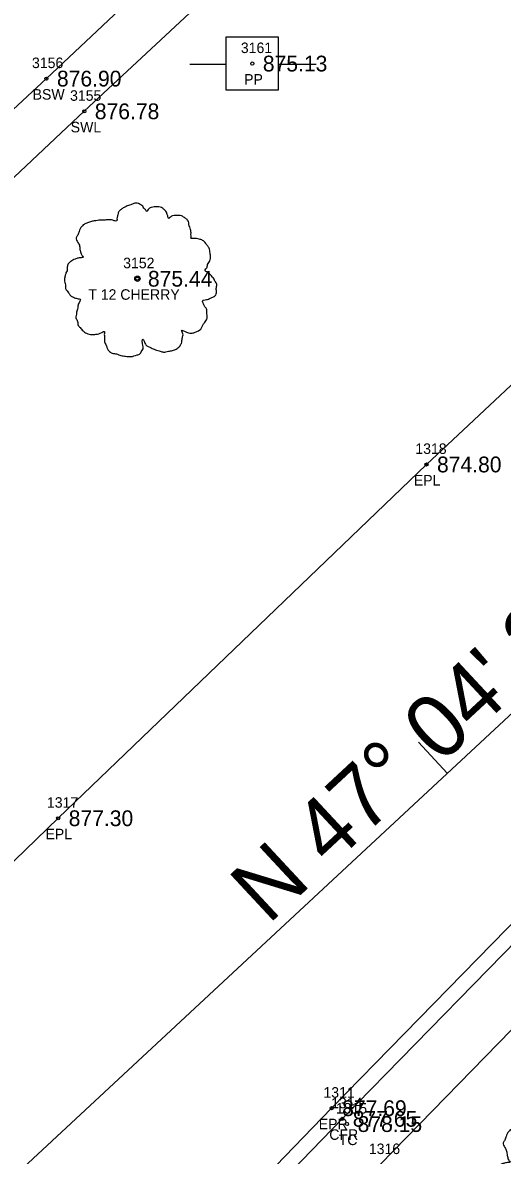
# Model space of a CAD drawing. Extents: x 1622501 to 1626664, y 1117816 to 1121579.
# Drawn here: x 1623728.6 to 1623774.2, y 1119016.9 to 1119124.7 of the extents above; entities that cross this region are included whole.
import ezdxf

# ---------------------------------------------------------------- set-up
doc = ezdxf.new("R2010")
doc.units = 0
for name, color, linetype in [('RD_EX_Conc', 7, 'Continuous'), ('RD_EX_Conc_txCode', 7, 'Continuous'), ('RD_EX_Road', 7, 'Continuous'), ('RD_EX_Road_txCode', 7, 'Continuous'), ('RD_EX_TX_Conc_ELEV', 7, 'Continuous'), ('RD_EX_TX_Road_ELEV', 7, 'Continuous'), ('RD_EX_TX_VEG_ELEV', 7, 'Continuous'), ('RD_EX_UT', 7, 'Continuous'), ('RD_EX_UT_txCode', 7, 'Continuous'), ('RD_EX_VEG', 7, 'Continuous'), ('RD_EX_VEG_txCode', 7, 'Continuous'), ('RD_HC_Cl', 7, 'Continuous'), ('RD_HC_Data', 7, 'Continuous'), ('RD_HC_Data_Tic', 7, 'Continuous'), ('RD_HC_Survey_ELEV', 7, 'Continuous'), ('RD_SMD_Locator', 7, 'Continuous')]:
    doc.layers.add(name, color=color, linetype=linetype)

msp = doc.modelspace()

# ---------------------------------------------------------------- linework, layer by layer
at = {"layer": 'RD_EX_Conc'}
for points in [[(1623595.96, 1118993.1), (1623622.15, 1119017.61), (1623656.16, 1119049.38), (1623694.84, 1119085.83), (1623730.88, 1119119.33), (1623767.2, 1119153.55), (1623807.43, 1119191.23), (1623857.13, 1119237.78)], [(1623598.76, 1118988.76), (1623625.5, 1119014.05), (1623659.65, 1119046.04), (1623697.95, 1119081.83), (1623734.48, 1119116.22), (1623770.4, 1119149.72), (1623810.51, 1119187.32), (1623859.03, 1119232.94)], [(1623723.66, 1118851.28), (1623685.69, 1118891.78), (1623680.28, 1118899.28), (1623678.54, 1118902.67), (1623678.54, 1118902.67), (1623675.57, 1118911.95), (1623675.05, 1118920.35), (1623676.57, 1118930.33), (1623679.23, 1118937.18), (1623684.43, 1118944.64), (1623689.98, 1118950.42), (1623724.5, 1118984.8), (1623759.01, 1119020.42), (1623793.7, 1119055.91), (1623829.35, 1119090.86), (1623865.61, 1119125.13), (1623901.92, 1119159.18), (1623933.22, 1119188.5)], [(1623676.3, 1118912.01), (1623681.21, 1118913.01), (1623680.58, 1118920.41), (1623681.86, 1118928.77), (1623684.24, 1118934.73), (1623688.55, 1118940.79), (1623694.15, 1118946.67), (1623728.27, 1118980.63), (1623762.62, 1119016.07), (1623797.56, 1119051.92), (1623833.1, 1119086.63), (1623869.15, 1119120.8), (1623905.55, 1119155), (1623936.97, 1119184.35), (1623933.79, 1119188.03)]]:
    msp.add_lwpolyline(points, dxfattribs=at)
at = {"layer": 'RD_EX_Road'}
for points in [[(1623722.97, 1118850.61), (1623684.95, 1118891.23), (1623679.41, 1118898.68), (1623674.26, 1118911.53), (1623673.5, 1118920.18), (1623675.21, 1118930.83), (1623677.99, 1118937.82), (1623683.61, 1118945.52), (1623688.81, 1118951.26), (1623723.47, 1118985.72), (1623758, 1119021.43), (1623792.69, 1119056.92), (1623828.41, 1119091.92), (1623864.6, 1119126.19), (1623900.88, 1119160.22), (1623932.37, 1119189.42), (1623932.63, 1119189.22), (1623935.82, 1119192.17), (1623973.77, 1119227.77), (1623990.87, 1119243.54), (1624009.99, 1119262.02), (1624046.29, 1119296.15)], [(1623613.19, 1119042.02), (1623611.01, 1119043.81), (1623609, 1119042.95), (1623599.73, 1119032.63), (1623594.94, 1119023.41), (1623593.06, 1119016.81), (1623592.29, 1119005.79), (1623594.79, 1118992.8), (1623599.51, 1118985.89), (1623605.79, 1118978.9), (1623613.54, 1118973.35), (1623625.91, 1118968.98), (1623636.84, 1118968.46), (1623647.74, 1118971.19), (1623659.46, 1118979.46), (1623658.89, 1118980.17), (1623658.34, 1118980.44), (1623666.32, 1118985.51), (1623695.7, 1119013.85), (1623732, 1119049), (1623767.02, 1119082.64), (1623805.04, 1119118.25), (1623840.27, 1119151.62), (1623856.19, 1119167.06)]]:
    msp.add_lwpolyline(points, dxfattribs=at)
at = {"layer": 'RD_EX_UT'}
for p, q in [((1623752.95, 1119123.27), (1623747.95, 1119123.27)), ((1623747.95, 1119123.27), (1623747.95, 1119118.27)), ((1623752.95, 1119118.27), (1623752.95, 1119123.27)), ((1623744.52, 1119120.71), (1623747.99, 1119120.71)), ((1623752.88, 1119120.71), (1623756.52, 1119120.71)), ((1623747.95, 1119118.27), (1623752.95, 1119118.27))]:
    msp.add_line(p, q, dxfattribs=at)
at = {"layer": 'RD_EX_VEG'}
for centre, radius in [((1623739.53, 1119100.3), 0.25), ((1623739.52, 1119100.28), 0.0001)]:
    msp.add_circle(centre, radius, dxfattribs=at)
for points in [[(1623739.66, 1119107.47), (1623739.36, 1119107.49), (1623739.04, 1119107.39), (1623738.79, 1119107.29), (1623738.56, 1119107.22), (1623738.34, 1119107.12), (1623738.04, 1119106.94), (1623737.81, 1119106.74), (1623737.69, 1119106.49), (1623737.64, 1119106.27), (1623737.59, 1119105.99), (1623737.59, 1119105.82), (1623737.46, 1119105.79), (1623737.31, 1119105.82), (1623737.06, 1119105.89), (1623736.81, 1119105.89), (1623736.56, 1119105.89), (1623736.21, 1119105.87), (1623735.86, 1119105.87), (1623735.59, 1119105.82), (1623735.26, 1119105.77), (1623734.89, 1119105.64), (1623734.54, 1119105.52), (1623734.24, 1119105.27), (1623733.99, 1119104.8), (1623733.86, 1119104.45), (1623733.71, 1119104.2), (1623733.86, 1119103.75), (1623734.04, 1119103.4), (1623734.06, 1119103.2), (1623734.14, 1119102.77), (1623734.24, 1119102.55), (1623734.36, 1119102.35), (1623734.29, 1119102.32), (1623733.91, 1119102.27), (1623733.61, 1119102.17), (1623733.19, 1119101.95), (1623732.96, 1119101.72), (1623732.86, 1119101.4), (1623732.84, 1119101.05), (1623732.74, 1119100.85), (1623732.66, 1119100.57), (1623732.64, 1119100.5), (1623732.59, 1119100.17), (1623732.69, 1119099.72), (1623732.71, 1119099.37), (1623732.84, 1119099.15), (1623732.99, 1119098.97), (1623733.16, 1119098.72), (1623733.56, 1119098.5), (1623733.89, 1119098.4), (1623734.09, 1119098.37), (1623733.91, 1119097.87), (1623733.86, 1119097.52), (1623733.74, 1119097.12), (1623733.74, 1119097.05), (1623733.69, 1119096.57), (1623733.84, 1119096.25), (1623733.91, 1119095.87), (1623734.09, 1119095.65), (1623734.36, 1119095.35), (1623734.69, 1119095.12), (1623735.19, 1119095), (1623735.59, 1119095.02), (1623736.16, 1119095.2), (1623736.41, 1119095.27), (1623736.39, 1119095.1), (1623736.41, 1119094.72), (1623736.41, 1119094.3), (1623736.56, 1119093.97), (1623736.66, 1119093.7), (1623736.81, 1119093.45), (1623737.14, 1119093.23), (1623737.54, 1119093.15), (1623737.96, 1119093), (1623738.41, 1119092.93), (1623738.91, 1119092.9), (1623739.51, 1119093.05), (1623739.79, 1119093.18), (1623739.89, 1119093.35), (1623740.09, 1119093.73), (1623740.04, 1119093.95), (1623740.06, 1119094.55), (1623740.16, 1119094.37), (1623740.34, 1119094.02), (1623740.84, 1119093.73), (1623741.24, 1119093.55), (1623741.71, 1119093.4), (1623742.01, 1119093.33), (1623742.49, 1119093.4), (1623742.86, 1119093.48), (1623743.23, 1119093.6), (1623743.53, 1119093.87), (1623743.71, 1119094.15), (1623743.76, 1119094.42), (1623743.83, 1119094.8), (1623743.88, 1119094.97)], [(1623743.88, 1119094.97), (1623743.81, 1119095.15), (1623743.76, 1119095.4), (1623743.83, 1119095.37), (1623744.01, 1119095.32), (1623744.28, 1119095.2), (1623744.51, 1119095.12), (1623744.83, 1119095.15), (1623745.11, 1119095.25), (1623745.56, 1119095.52), (1623745.83, 1119096), (1623746.11, 1119096.4), (1623746.18, 1119096.72), (1623746.13, 1119096.95), (1623746.11, 1119097.45), (1623745.91, 1119097.7), (1623745.86, 1119097.82), (1623745.76, 1119098.22), (1623745.83, 1119098.27), (1623746.11, 1119098.32), (1623746.48, 1119098.45), (1623746.76, 1119098.57), (1623746.98, 1119098.75), (1623747.06, 1119098.97), (1623747.03, 1119099.37), (1623747.08, 1119099.77), (1623747.01, 1119099.92), (1623746.91, 1119100.07), (1623746.83, 1119100.27), (1623746.68, 1119100.42), (1623746.58, 1119100.57), (1623746.48, 1119100.67), (1623746.36, 1119100.82), (1623746.18, 1119100.95), (1623746.03, 1119101), (1623745.98, 1119101.15), (1623746.13, 1119101.35), (1623746.18, 1119101.45), (1623746.21, 1119101.67), (1623746.43, 1119102.02), (1623746.48, 1119102.42), (1623746.43, 1119102.85), (1623746.38, 1119103.12), (1623746.23, 1119103.4), (1623746.03, 1119103.65), (1623745.91, 1119103.82), (1623745.73, 1119103.95), (1623745.41, 1119104.07), (1623745.16, 1119104.12), (1623744.81, 1119104.12), (1623744.61, 1119104.17), (1623744.63, 1119104.22), (1623744.63, 1119104.37), (1623744.63, 1119104.65), (1623744.56, 1119105.1), (1623744.41, 1119105.59), (1623744.41, 1119105.62), (1623744.31, 1119105.87), (1623744.08, 1119106.07), (1623743.91, 1119106.17), (1623743.71, 1119106.29), (1623743.46, 1119106.32), (1623743.16, 1119106.32), (1623742.88, 1119106.27), (1623742.68, 1119106.17), (1623742.51, 1119106.04), (1623742.44, 1119106.19), (1623742.34, 1119106.49), (1623742.29, 1119106.64), (1623742.14, 1119106.82), (1623741.91, 1119107.02), (1623741.46, 1119107.14), (1623740.84, 1119107.07), (1623740.54, 1119106.87), (1623740.39, 1119106.69), (1623740.34, 1119106.82), (1623740.14, 1119107.02), (1623740.04, 1119107.19), (1623739.86, 1119107.32), (1623739.71, 1119107.42), (1623739.61, 1119107.47)], [(1623780.27, 1119021.42), (1623779.97, 1119021.45), (1623779.64, 1119021.35), (1623779.39, 1119021.25), (1623779.17, 1119021.17), (1623778.94, 1119021.07), (1623778.64, 1119020.9), (1623778.42, 1119020.7), (1623778.29, 1119020.45), (1623778.24, 1119020.22), (1623778.19, 1119019.95), (1623778.19, 1119019.77), (1623778.07, 1119019.75), (1623777.92, 1119019.77), (1623777.67, 1119019.85), (1623777.42, 1119019.85), (1623777.17, 1119019.85), (1623776.82, 1119019.82), (1623776.47, 1119019.82), (1623776.19, 1119019.77), (1623775.87, 1119019.72), (1623775.49, 1119019.6), (1623775.14, 1119019.47), (1623774.84, 1119019.22), (1623774.59, 1119018.75), (1623774.47, 1119018.4), (1623774.32, 1119018.15), (1623774.47, 1119017.7), (1623774.64, 1119017.35), (1623774.67, 1119017.15), (1623774.74, 1119016.73), (1623774.84, 1119016.5), (1623774.97, 1119016.3), (1623774.89, 1119016.28), (1623774.52, 1119016.23), (1623774.22, 1119016.13), (1623773.79, 1119015.9), (1623773.57, 1119015.68), (1623773.47, 1119015.35), (1623773.44, 1119015), (1623773.34, 1119014.8), (1623773.27, 1119014.53), (1623773.24, 1119014.45), (1623773.19, 1119014.13), (1623773.29, 1119013.68), (1623773.32, 1119013.33), (1623773.44, 1119013.1), (1623773.59, 1119012.93), (1623773.77, 1119012.68), (1623774.17, 1119012.45), (1623774.49, 1119012.35), (1623774.69, 1119012.33), (1623774.52, 1119011.83), (1623774.47, 1119011.48), (1623774.34, 1119011.08), (1623774.34, 1119011), (1623774.29, 1119010.53), (1623774.44, 1119010.2), (1623774.52, 1119009.83), (1623774.69, 1119009.6), (1623774.97, 1119009.3), (1623775.29, 1119009.08), (1623775.79, 1119008.95), (1623776.19, 1119008.98), (1623776.77, 1119009.15), (1623777.02, 1119009.23), (1623776.99, 1119009.05), (1623777.02, 1119008.68), (1623777.02, 1119008.25), (1623777.17, 1119007.93), (1623777.27, 1119007.65), (1623777.42, 1119007.4), (1623777.74, 1119007.18), (1623778.14, 1119007.1), (1623778.57, 1119006.95), (1623779.02, 1119006.88), (1623779.52, 1119006.85), (1623780.12, 1119007), (1623780.39, 1119007.13), (1623780.49, 1119007.3), (1623780.69, 1119007.68), (1623780.64, 1119007.9), (1623780.67, 1119008.5), (1623780.77, 1119008.33), (1623780.94, 1119007.98), (1623781.44, 1119007.68), (1623781.84, 1119007.5), (1623782.31, 1119007.35), (1623782.61, 1119007.28), (1623783.09, 1119007.35), (1623783.46, 1119007.43), (1623783.84, 1119007.55), (1623784.14, 1119007.83), (1623784.31, 1119008.1), (1623784.36, 1119008.38), (1623784.44, 1119008.75), (1623784.49, 1119008.93)]]:
    msp.add_spline(points, degree=3, dxfattribs=at)
at = {"layer": 'RD_HC_Cl'}
msp.add_line((1623608.84, 1118904.32), (1623937.25, 1119209.79), dxfattribs=at)
at = {"layer": 'RD_HC_Data_Tic'}
msp.add_line((1623769, 1119053.29), (1623766.27, 1119056.22), dxfattribs=at)
at = {"layer": 'RD_SMD_Locator'}
for centre in [(1623750.46, 1119120.76), (1623730.88, 1119119.33), (1623734.48, 1119116.22), (1623739.53, 1119100.3), (1623767.02, 1119082.64), (1623732, 1119049), (1623758, 1119021.43), (1623759.01, 1119020.42), (1623759.47, 1119019.92)]:
    msp.add_circle(centre, 0.15, dxfattribs=at)

# ---------------------------------------------------------------- texts
at = {"layer": 'RD_EX_Conc_txCode'}
for s, p in [('3156', (1623729.51, 1119120.33)), ('BSW', (1623729.57, 1119117.33)), ('3155', (1623733.13, 1119117.22)), ('SWL', (1623733.19, 1119114.22)), ('1314', (1623757.95, 1119021.42)), ('1315', (1623758.4, 1119020.92)), ('CFR', (1623757.78, 1119018.42)), ('TC', (1623758.67, 1119017.92)), ('1316', (1623761.54, 1119017.07))]:
    msp.add_text(s, height=1, dxfattribs=at).set_placement(p)
at = {"layer": 'RD_EX_Road_txCode'}
for s, p in [('1318', (1623765.96, 1119083.64)), ('EPL', (1623765.82, 1119080.64)), ('1317', (1623730.93, 1119050)), ('EPL', (1623730.79, 1119047)), ('1311', (1623757.22, 1119022.43)), ('EPR', (1623756.77, 1119019.43))]:
    msp.add_text(s, height=1, dxfattribs=at).set_placement(p)
at = {"layer": 'RD_EX_TX_Conc_ELEV'}
for s, p in [('876.90', (1623731.88, 1119118.58)), ('876.78', (1623735.48, 1119115.47)), ('877.65', (1623760.01, 1119019.67)), ('878.15', (1623760.47, 1119019.17))]:
    msp.add_text(s, height=1.5, dxfattribs=at).set_placement(p)
at = {"layer": 'RD_EX_TX_Road_ELEV'}
for s, p in [('874.80', (1623768.02, 1119081.89)), ('877.30', (1623733, 1119048.25)), ('877.69', (1623759, 1119020.68))]:
    msp.add_text(s, height=1.5, dxfattribs=at).set_placement(p)
at = {"layer": 'RD_EX_TX_VEG_ELEV'}
msp.add_text('875.44', height=1.5, dxfattribs=at).set_placement((1623740.53, 1119099.55))
at = {"layer": 'RD_EX_UT_txCode'}
for s, p in [('3161', (1623749.37, 1119121.76)), ('PP', (1623749.68, 1119118.76))]:
    msp.add_text(s, height=1, dxfattribs=at).set_placement(p)
at = {"layer": 'RD_EX_VEG_txCode'}
for s, p in [('3152', (1623738.18, 1119101.3)), ('T 12 CHERRY', (1623734.86, 1119098.3))]:
    msp.add_text(s, height=1, dxfattribs=at).set_placement(p)
at = {"layer": 'RD_HC_Data'}
msp.add_text('N 47%%d 04\' 21" E', height=6, rotation=42.9276, dxfattribs=at).set_placement((1623751.97, 1119038.82))
at = {"layer": 'RD_HC_Survey_ELEV'}
msp.add_text('875.13', height=1.5, dxfattribs=at).set_placement((1623751.46, 1119120.01))

doc.saveas('drawing.dxf')
